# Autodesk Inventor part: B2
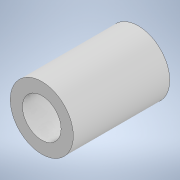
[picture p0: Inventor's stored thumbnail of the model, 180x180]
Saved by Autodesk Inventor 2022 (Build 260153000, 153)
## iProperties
Created: 2024-12
Part Number: B2
Material: 一般
Document SubType Name: Modeling
Designer: jsat7
Density: 1 g/cm^3
Appearance: 既定
Author: jsat7
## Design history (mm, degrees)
sketch "スケッチ1"
  geometry: C1 r 2.45 at (0, 0); C2 r 1.5 at (0, 0); 1 further point
  constraints: 2 centre point, 2 coincident
  dimensions: "d0" = 4.9 diameter of C1; "d1" = 3 diameter of C2
extrude "押し出し1" new body sketch "スケッチ1" distance "d2" = 7.5; taper "d3" = 0 deg
node "ソリッド1"
